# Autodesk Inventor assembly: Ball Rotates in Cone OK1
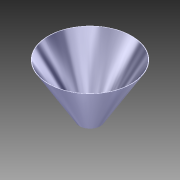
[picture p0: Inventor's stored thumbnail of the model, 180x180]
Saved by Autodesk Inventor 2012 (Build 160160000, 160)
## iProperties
Created: 2012-03
Part Number: Ball Rotates in Cone OK1
Document SubType Name: Assembly
Designer: Jonathan
Author: Jonathan
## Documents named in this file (3)
- C:\AUTODESK WORKS\FORUM\Ball Rotates in Cone OK1.iam
- C:\AUTODESK WORKS\FORUM\Cone.ipt
- C:\AUTODESK WORKS\FORUM\Ball1.ipt
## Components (2 placed, 2 different names)
1. Cone:1 — Tangent:1
2. Ball1:1 — Tangent:1
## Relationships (1: Tangent 1)
- Tangent:1: Cone:1 ↔ Ball1:1
